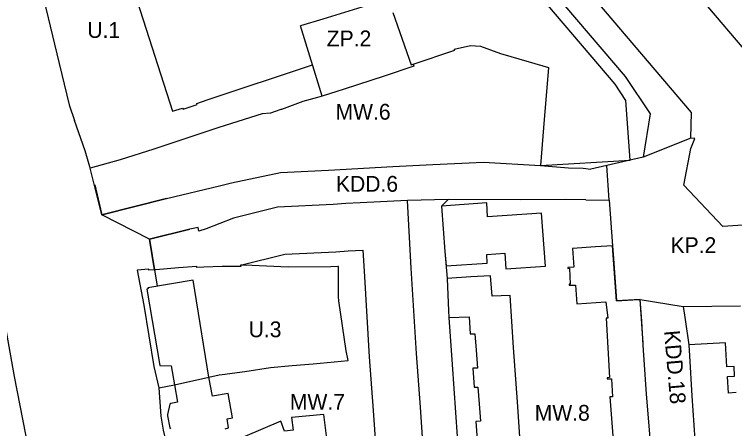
# Model space of a CAD drawing. Extents: x 7424719 to 7426158, y 5545504 to 5546892.
# Drawn here: x 7425140.3 to 7425368.6, y 5546128 to 5546259.1 of the extents above; entities that cross this region are included whole.
import ezdxf

# ---------------------------------------------------------------- set-up
doc = ezdxf.new("R2010")
doc.units = 0
for name, color, linetype in [('Linia Zabudowy Nieprzekraczalna', 7, 'Continuous'), ('Linia Zabudowy Obowiązujaca', 7, 'Continuous'), ('Linie Rozgraniczajace', 7, 'Continuous'), ('Oznaczenia Przeznaczenia', 7, 'Continuous')]:
    doc.layers.add(name, color=color, linetype=linetype)

msp = doc.modelspace()

# ---------------------------------------------------------------- linework, layer by layer
at = {"layer": 'Linia Zabudowy Nieprzekraczalna'}
msp.add_line((7425201.36, 5546232.03), (7425234.81, 5546243.12), dxfattribs=at)
for points in [[(7425334.12, 5546231.87), (7425330.7, 5546236.97), (7425277.09, 5546300.01), (7425258.76, 5546310.8), (7425243.13, 5546314.34), (7425242.76, 5546314.24)], [(7425335.49, 5546212.94), (7425334.12, 5546231.87)], [(7425212.01, 5546179.74), (7425225.99, 5546183.13), (7425242.21, 5546183.96), (7425246.15, 5546184.21), (7425250.74, 5546184.42)], [(7425250.74, 5546184.42), (7425251.13, 5546177.81), (7425252.8, 5546150.67), (7425254.02, 5546133.7), (7425255.14, 5546117.09), (7425257.31, 5546104.5), (7425259.48, 5546092.73), (7425262.32, 5546075.49)]]:
    msp.add_lwpolyline(points, dxfattribs=at)
at = {"layer": 'Linia Zabudowy Obowiązujaca'}
for points in [[(7425177.8, 5546304.93), (7425176.73, 5546308.26), (7425176.61, 5546308.52), (7425173.45, 5546307.58), (7425173.34, 5546307.88), (7425168.78, 5546306.42), (7425168.81, 5546306.09), (7425165.69, 5546304.97), (7425176.94, 5546270.19), (7425174.7, 5546269.52), (7425176.86, 5546262.47), (7425179.19, 5546263.22), (7425190.44, 5546228.41), (7425193.63, 5546229.37), (7425193.77, 5546229.04), (7425198.26, 5546230.53), (7425198.17, 5546230.85), (7425201.36, 5546232.03)], [(7425165.84, 5546205.13), (7425168.02, 5546195.67), (7425188.47, 5546200.8), (7425205.36, 5546204.79), (7425209.08, 5546205.71), (7425224.67, 5546209.02), (7425239.91, 5546209.76), (7425260.22, 5546210.91), (7425272.94, 5546211.52), (7425288.97, 5546212.29), (7425307.03, 5546211.28), (7425335.49, 5546212.94)], [(7425270.05, 5546118.88), (7425268.98, 5546134.74), (7425267.77, 5546151.67), (7425266.1, 5546178.71), (7425264.86, 5546200.15), (7425249.94, 5546199.4), (7425245.34, 5546199.19), (7425241.35, 5546198.94), (7425223.75, 5546198.03), (7425209.79, 5546194.52), (7425201.08, 5546191.15), (7425198.81, 5546190.5), (7425198.54, 5546191.66), (7425195.96, 5546191.04), (7425183.17, 5546187.94), (7425185.6, 5546173.03)], [(7425342.39, 5546118.73), (7425340.7, 5546138.86), (7425339.64, 5546154.38), (7425339.6, 5546154.97), (7425338.66, 5546168.81), (7425331.14, 5546168.35), (7425329.92, 5546185.86), (7425324.49, 5546185.49), (7425317.16, 5546185), (7425317.63, 5546179.1), (7425315.77, 5546179), (7425315.77, 5546178.68), (7425316.26, 5546178.71), (7425316.47, 5546173.67), (7425316.13, 5546173.64), (7425316.14, 5546173.34), (7425318.11, 5546173.36), (7425318.55, 5546167.42), (7425327.77, 5546168.1), (7425328.44, 5546162.93), (7425327.89, 5546162.93), (7425328.9, 5546144.09), (7425328.18, 5546144.06), (7425328.21, 5546143.65), (7425329.53, 5546143.7), (7425329.92, 5546138), (7425329.07, 5546138), (7425330.4, 5546120.21)], [(7425300.93, 5546119.01), (7425299.73, 5546136.42), (7425298.54, 5546153.62), (7425297.41, 5546170.1), (7425291.72, 5546169.88), (7425291.23, 5546176.32), (7425284.94, 5546175.95), (7425277.45, 5546175.51), (7425277.95, 5546165.18), (7425278.05, 5546163.1), (7425284.5, 5546163.36), (7425284.82, 5546157.99), (7425286.27, 5546157.98), (7425286.67, 5546152.73), (7425287.09, 5546147.12), (7425285.58, 5546147.03), (7425286.04, 5546141.11), (7425287.16, 5546141.06), (7425287.61, 5546135.77), (7425288.07, 5546130.29), (7425286.58, 5546130.21), (7425287.01, 5546124.35)], [(7425207.11, 5546127.86), (7425208.21, 5546128.19), (7425207.73, 5546131.04), (7425209.45, 5546131.37), (7425208.08, 5546139.07), (7425203.07, 5546138.17), (7425201.93, 5546144.2), (7425196.97, 5546174.95), (7425182.62, 5546172.53), (7425182.66, 5546172.17), (7425182.28, 5546172.09), (7425186.44, 5546147.89), (7425190.03, 5546147.84), (7425191.04, 5546141.82), (7425191.04, 5546141.82), (7425192.01, 5546136.32), (7425189.87, 5546135.92), (7425189.6, 5546135.68), (7425188.84, 5546132.38), (7425188.85, 5546131.95), (7425189.6, 5546128.24), (7425189.74, 5546127.88)], [(7425369.07, 5546139.39), (7425366.62, 5546139.21), (7425366.33, 5546144.46), (7425368.56, 5546144.55), (7425368.44, 5546147.6), (7425366.17, 5546147.5), (7425365.76, 5546155.11), (7425354.06, 5546154.47), (7425354.28, 5546150.95), (7425355.06, 5546138.36), (7425355.96, 5546124.38), (7425357.04, 5546110.63), (7425357.97, 5546095.98), (7425358.34, 5546091.86), (7425358.04, 5546091.86), (7425358.84, 5546081.44), (7425359.17, 5546081.45), (7425359.48, 5546077.35), (7425359.96, 5546077.38), (7425363.56, 5546077.63), (7425363.55, 5546077.33), (7425375.97, 5546078.17)]]:
    msp.add_lwpolyline(points, dxfattribs=at)
for points in [[(7425295.78, 5546183.47), (7425296.1, 5546178.56), (7425308.65, 5546179.32), (7425307.41, 5546196.16), (7425290.28, 5546195), (7425290.08, 5546199.47), (7425275.72, 5546198.37), (7425276.73, 5546184.03), (7425277.19, 5546179.43), (7425290.11, 5546180.31), (7425290.07, 5546183.06)], [(7425228.13, 5546131.48), (7425228.66, 5546127.5), (7425225.93, 5546127.17), (7425224.8, 5546130.28), (7425213.38, 5546125.46), (7425217.36, 5546116.51), (7425220.08, 5546115.44), (7425227.38, 5546118.9), (7425229.69, 5546118.97), (7425230.26, 5546114.86), (7425232.94, 5546115.2), (7425235.47, 5546094.36), (7425242.87, 5546094.77), (7425240.98, 5546110.77), (7425240.35, 5546116.38), (7425238.38, 5546132.42)]]:
    msp.add_lwpolyline(points, close=True, dxfattribs=at)
at = {"layer": 'Linie Rozgraniczajace'}
for p, q in [((7425978.47, 5545533.55), (7425205.67, 5546443.4)), ((7425237.84, 5546233.22), (7425231.04, 5546255.45)), ((7425341.81, 5546227.58), (7425339.62, 5546213.89)), ((7425354.71, 5546219.91), (7425339.62, 5546213.89)), ((7425168.02, 5546195.67), (7425164.3, 5546210.37)), ((7425328.88, 5546200.24), (7425328.1, 5546211.25)), ((7425188.47, 5546200.8), (7425168.02, 5546195.67)), ((7425183.17, 5546187.94), (7425168.02, 5546195.67)), ((7425185.15, 5546178.26), (7425184.9, 5546178.24)), ((7425200.35, 5546179.02), (7425198.15, 5546178.92)), ((7425339.16, 5546161.97), (7425338.66, 5546168.81))]:
    msp.add_line(p, q, dxfattribs=at)
for points in [[(7425241.58, 5546318.06), (7425243.02, 5546318.47), (7425251.63, 5546316.51), (7425260.25, 5546314.56), (7425279.7, 5546303.12), (7425306.8, 5546271.25), (7425333.9, 5546239.39), (7425341.81, 5546227.58)], [(7425167.7, 5546307.07), (7425166.3, 5546306.1), (7425157.27, 5546297.21), (7425153.88, 5546291.79), (7425152.5, 5546289.77), (7425150.14, 5546284.54), (7425148.8, 5546279.34), (7425148.35, 5546273.48), (7425148.92, 5546266.87), (7425153.77, 5546246.63), (7425157.7, 5546230.44), (7425159.39, 5546225.48)], [(7425354.92, 5546228.03), (7425302.89, 5546289.28), (7425298.52, 5546302.6), (7425296.58, 5546305.15)], [(7425254.53, 5546262.65), (7425238.04, 5546257.6), (7425231.04, 5546255.45)], [(7425260.27, 5546259.68), (7425266.02, 5546243.08), (7425266.67, 5546243.3), (7425266.9, 5546242.65), (7425257.52, 5546239.5), (7425244.82, 5546235.44), (7425237.84, 5546233.22), (7425236.41, 5546232.76), (7425231.77, 5546231.5), (7425224.96, 5546229.02), (7425224.74, 5546228.95), (7425222.94, 5546228.34), (7425221.44, 5546227.84), (7425218.85, 5546227.63), (7425205.1, 5546223.27), (7425184.49, 5546216.41), (7425173.85, 5546213.07), (7425168.13, 5546211.43), (7425164.3, 5546210.37), (7425164.17, 5546210.81), (7425162.68, 5546215.86), (7425159.39, 5546225.48)], [(7425266.67, 5546243.3), (7425279.86, 5546247.73), (7425279.71, 5546248.12), (7425284.87, 5546249.27), (7425288.08, 5546248.99), (7425294.36, 5546246.71), (7425303.47, 5546244.03), (7425309.65, 5546242.22), (7425308.02, 5546223.14), (7425307.03, 5546211.28)], [(7425364.88, 5546191.88), (7425352.48, 5546204.98), (7425354.72, 5546216.63), (7425356, 5546219.76), (7425354.71, 5546219.91), (7425354.92, 5546228.03)], [(7425188.47, 5546200.8), (7425205.36, 5546204.79), (7425209.08, 5546205.71), (7425224.67, 5546209.02), (7425239.91, 5546209.76), (7425260.22, 5546210.91), (7425272.94, 5546211.52), (7425288.97, 5546212.29), (7425307.03, 5546211.28), (7425315.97, 5546210.47), (7425320.58, 5546210.37), (7425323.07, 5546210.09)], [(7425339.62, 5546213.89), (7425328.1, 5546211.25), (7425323.07, 5546210.09)], [(7425321.47, 5546200.35), (7425315.03, 5546200.43), (7425300.73, 5546200.39), (7425277.79, 5546200.47), (7425264.86, 5546200.15), (7425249.94, 5546199.4), (7425245.34, 5546199.19), (7425241.35, 5546198.94), (7425223.75, 5546198.03), (7425209.79, 5546194.52), (7425201.08, 5546191.15), (7425198.81, 5546190.5), (7425198.54, 5546191.66), (7425195.96, 5546191.04)], [(7425277.79, 5546200.47), (7425275.72, 5546198.37), (7425276.74, 5546184.06), (7425277.45, 5546175.51), (7425277.95, 5546165.18), (7425278.05, 5546163.1), (7425279.08, 5546148.23), (7425280.6, 5546125.4), (7425282.6, 5546112.98), (7425285.15, 5546096.74), (7425287.21, 5546083.56), (7425288.75, 5546073.55), (7425290.07, 5546066.27), (7425291.94, 5546065), (7425279.6, 5546062.26), (7425277.16, 5546077.67), (7425274.26, 5546095.31), (7425272.08, 5546107.14), (7425270.05, 5546118.88), (7425268.98, 5546134.74), (7425267.77, 5546151.67), (7425266.1, 5546178.71), (7425264.86, 5546200.15)], [(7425321.47, 5546200.35), (7425328.88, 5546200.24), (7425329.92, 5546185.86), (7425330.21, 5546181.76), (7425331.14, 5546168.35), (7425336.29, 5546168.67), (7425338.66, 5546168.81), (7425352.24, 5546166.59), (7425370.49, 5546166.85)], [(7425413.86, 5546145.47), (7425383.99, 5546185.44), (7425382.18, 5546187.57), (7425379.14, 5546192.91), (7425364.88, 5546191.88)], [(7425184.75, 5546178.23), (7425183.17, 5546187.94), (7425195.96, 5546191.04)], [(7425138.58, 5546107.76), (7425141.26, 5546108.56), (7425143.23, 5546109.81), (7425145.37, 5546113.16), (7425145.74, 5546116.86), (7425140.37, 5546144.43), (7425138.59, 5546153.92), (7425132.46, 5546188.04)], [(7425206.19, 5546145.09), (7425213.34, 5546146.01), (7425221.53, 5546147.32), (7425228.36, 5546147.88), (7425235.05, 5546148.47), (7425246.12, 5546149.54), (7425245.5, 5546152.61), (7425243.09, 5546168.39), (7425243, 5546169.61), (7425243.05, 5546173.08), (7425243.05, 5546179.26), (7425242.81, 5546179.26), (7425240.56, 5546179.2), (7425227.12, 5546179.1), (7425213.38, 5546179.68), (7425212.01, 5546179.74), (7425212.07, 5546179.28), (7425206.19, 5546179.28), (7425200.35, 5546179.02)], [(7425184.9, 5546178.24), (7425184.75, 5546178.23), (7425182.9, 5546178.09), (7425182.88, 5546178.4), (7425179.25, 5546178.09), (7425181.33, 5546167.03), (7425184.45, 5546147.57), (7425186.07, 5546140.83), (7425191.06, 5546141.82), (7425201.93, 5546144.2), (7425205.21, 5546144.97), (7425206.19, 5546145.09)], [(7425198.15, 5546178.92), (7425198.12, 5546179.27), (7425192.32, 5546178.82), (7425185.15, 5546178.26)], [(7425352.24, 5546166.59), (7425352.93, 5546162.53), (7425354.06, 5546154.47), (7425354.28, 5546150.95), (7425355.06, 5546138.36), (7425355.96, 5546124.38)], [(7425353.43, 5545954.16), (7425351.84, 5545977.5), (7425350.3, 5546001.51), (7425349, 5546021.38), (7425347.63, 5546041.36), (7425346.33, 5546062.25), (7425345.35, 5546077.46), (7425343.6, 5546101.07), (7425342.39, 5546118.73), (7425340.7, 5546138.86), (7425339.64, 5546154.38), (7425339.16, 5546161.97)], [(7425186.07, 5546140.83), (7425186.71, 5546131.91), (7425187.48, 5546127.49), (7425189.18, 5546120.29), (7425190.63, 5546118.51)]]:
    msp.add_lwpolyline(points, dxfattribs=at)

# ---------------------------------------------------------------- texts
at = {"layer": 'Oznaczenia Przeznaczenia'}
for s, p in [('U.1', (7425163.42, 5546251.64)), ('ZP.2', (7425239.3, 5546248.98)), ('MW.6', (7425242.09, 5546225.75)), ('KDD.6', (7425242.23, 5546202.94)), ('KP.2', (7425348.29, 5546183.52)), ('U.3', (7425214.55, 5546156.88)), ('MW.7', (7425227.62, 5546133.89)), ('MW.8', (7425305.24, 5546130.44))]:
    msp.add_text(s, height=5, dxfattribs=at).set_placement(p)
msp.add_text('KDD.18', height=5, rotation=274.9033, dxfattribs=at).set_placement((7425346.22, 5546158.87))

doc.saveas('drawing.dxf')
